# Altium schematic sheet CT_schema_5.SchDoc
size 421 x 246 mm
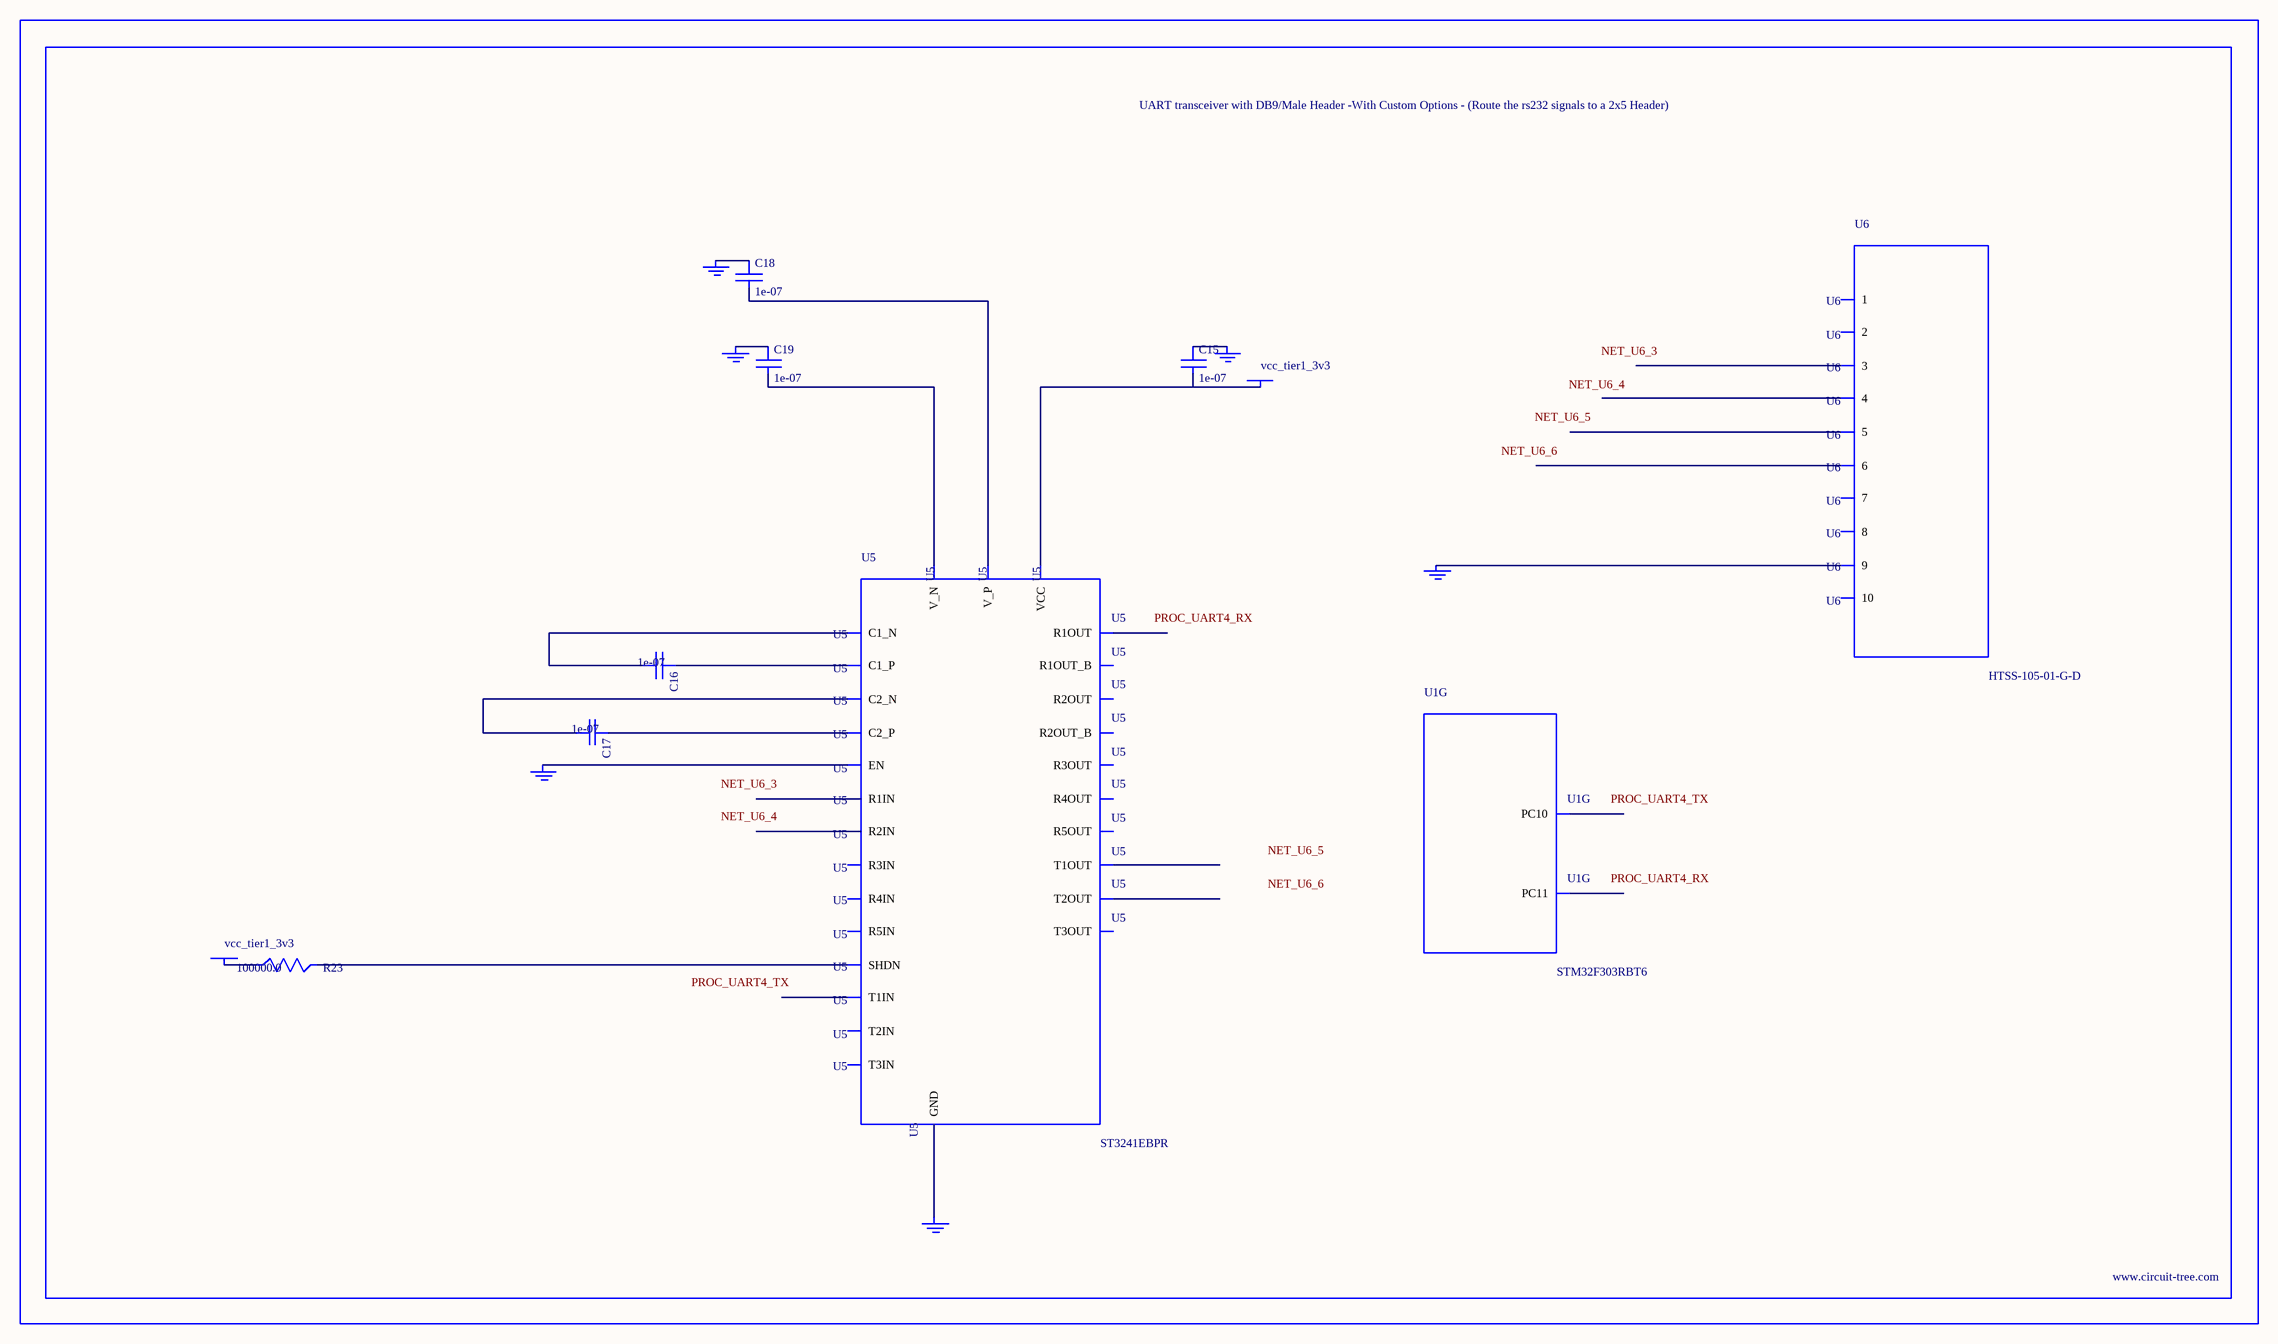
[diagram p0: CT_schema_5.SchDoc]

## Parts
BORDER4  (no value)
C15  1e-07  [C0402]
C16  1e-07  [C0402]
C17  1e-07  [C0402]
C18  1e-07  [C0402]
C19  1e-07  [C0402]
GND_INSTANCE_4_0  (no value)
GND_INSTANCE_4_1  (no value)
GND_INSTANCE_4_2  (no value)
GND_INSTANCE_4_3  (no value)
GND_INSTANCE_4_4  (no value)
GND_INSTANCE_4_5  (no value)
POWER_INSTANCE_4_0  vcc_tier1_3v3
POWER_INSTANCE_4_1  vcc_tier1_3v3
R23  100000.0  [R0603]
U1  STM32F303RBT6  [LQFP64]  (part G of 7)
U5  ST3241EBPR  [SSOP-28]
U6  HTSS-105-01-G-D  [HTSS-105-01-G-D]

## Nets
NetC15_1: C15.1 GND_INSTANCE_4_2.0(GND)
NetC15_2: C15.2 POWER_INSTANCE_4_1.0(PWR) U5.26(VCC)
NetC16_1: C16.1 U5.28(C1_P)
NetC16_2: C16.2 U5.24(C1_N)
NetC17_1: C17.1 U5.1(C2_P)
NetC17_2: C17.2 U5.2(C2_N)
NetC18_1: C18.1 GND_INSTANCE_4_3.0(GND)
NetC18_2: C18.2 U5.27(V_P)
NetC19_1: C19.1 GND_INSTANCE_4_0.0(GND)
NetC19_2: C19.2 U5.3(V_N)
NetGND_INSTANCE_4_1_0: GND_INSTANCE_4_1.0(GND) U5.23(EN)
NetGND_INSTANCE_4_4_0: GND_INSTANCE_4_4.0(GND) U5.25(GND)
NetGND_INSTANCE_4_5_0: GND_INSTANCE_4_5.0(GND) U6.9
NetPOWER_INSTANCE_4_0_0: POWER_INSTANCE_4_0.0(PWR) R23.1
NetR23_2: R23.2 U5.22(SHDN)

Not connected (* = marked no-connect by the designer): U1 51(PC10) 52(PC11); U5 4(R1IN) 5(R2IN) 6(R3IN) 7(R4IN) 8(R5IN) 9(T1OUT) 10(T2OUT) 11(T3OUT) 12(T3IN) 13(T2IN) 14(T1IN) 15(R5OUT) 16(R4OUT) 17(R3OUT) 18(R2OUT) 19(R1OUT) 20(R2OUT_B) 21(R1OUT_B); U6 1 2 3 4 5 6 7 8 10

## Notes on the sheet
- Labels drawn without touching a wire or pin: NET_U6_3, NET_U6_4, NET_U6_5, NET_U6_6, PROC_UART4_RX, PROC_UART4_TX

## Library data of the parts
BORDER4 = BORDER_PAGE4
C15-C19 = C0402C104K3RACTU
GND_INSTANCE_4_0-GND_INSTANCE_4_5 = GND
POWER_INSTANCE_4_0 POWER_INSTANCE_4_1 = PWR
R23 = RC0603JR-07100KL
